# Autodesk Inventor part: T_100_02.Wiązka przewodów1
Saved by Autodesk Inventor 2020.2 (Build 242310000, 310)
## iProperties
Key:2|1|1|0|4|0|0|0|2|0|0|0|Level:2: <CableProperty entityType="Connector" version="1.0"><ID editable="" value=""/><UserDefined/><Name editable="True" value=""/><Refdes editable="True" value="RC CO
Key:2|1|1|0|4|0|0|0|3|0|0|0|Level:2: <CableProperty entityType="Connector" version="1.0"><ID editable="" value=""/><UserDefined/><Name editable="True" value=""/><Refdes editable="True" value="RC CO
Manager: www.cadconsulting.pl
Company: Fabian Stasiak CAD Consulting
Created: 2014-09
Part Number: T_100_02.Wiązka przewodów1
Material: Ogólne
Document SubType Name: Modelowanie
Designer: F.Stasiak
Appearance: Ogólne
Catalog Web Link: www.expertbooks.pl
Author: F.Stasiak
Subject: Zbiór ćwiczeń. Autodesk Inventor 2020. Kurs Professional
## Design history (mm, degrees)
node "Korpusy bryłowe"
node "Korpusy powierzchniowe"
